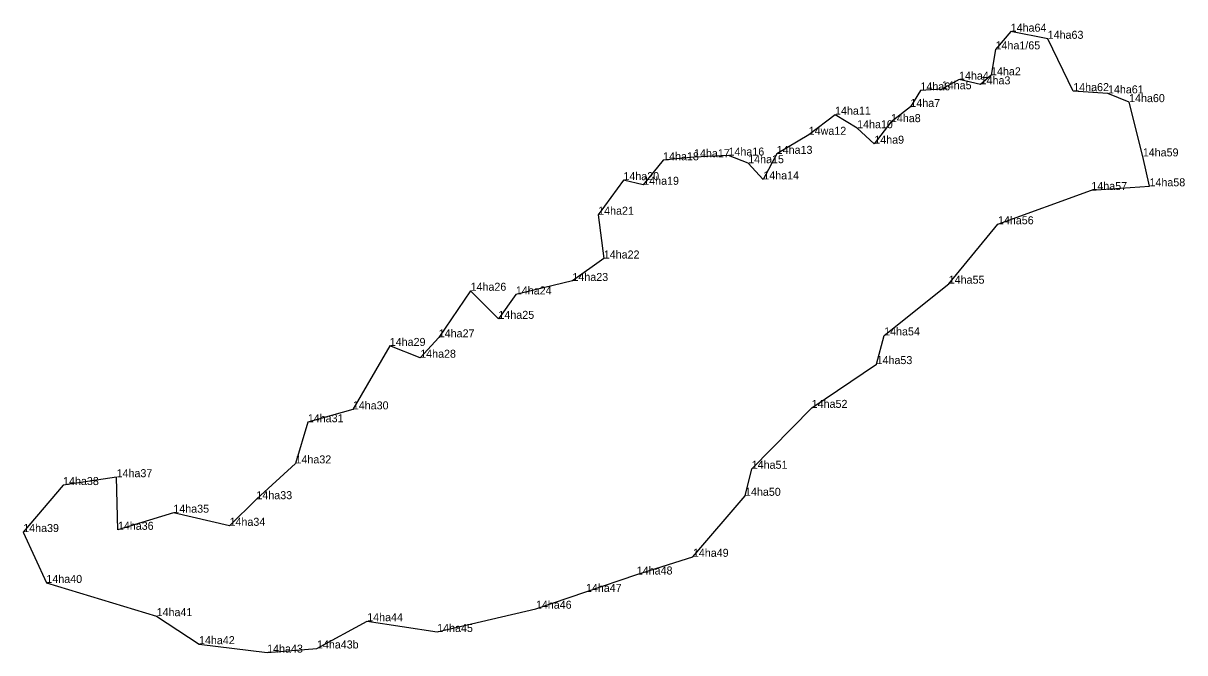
# Model space of a CAD drawing. Extents: x 2072529 to 2267990, y 436423 to 470008.
# Drawn here: x 2254865 to 2255590, y 442680 to 443073 of the extents above; entities that cross this region are included whole.
import ezdxf

# ---------------------------------------------------------------- set-up
doc = ezdxf.new("R2010")
doc.units = 0
doc.layers.add('Level 3', color=7, linetype='Continuous')
doc.layers.add('Old_Level_52', color=7, linetype='Continuous')

msp = doc.modelspace()

# ---------------------------------------------------------------- linework, layer by layer
at = {"layer": 'Level 3'}
for p, q in [((2255481.413, 443068.129), (2255481.413, 443068.129)), ((2255504.521, 443063.666), (2255504.521, 443063.666)), ((2255471.952, 443057.071), (2255471.952, 443057.071)), ((2255469.116, 443040.862), (2255469.116, 443040.862)), ((2255438.396, 443032.173), (2255438.396, 443032.173)), ((2255449.13, 443038.154), (2255449.13, 443038.154)), ((2255462.621, 443035.22), (2255462.621, 443035.22)), ((2255425.047, 443031.446), (2255425.047, 443031.446)), ((2255520.479, 443030.967), (2255520.479, 443030.967)), ((2255542.182, 443029.573), (2255542.182, 443029.573)), ((2255418.747, 443021.084), (2255418.747, 443021.084)), ((2255555.382, 443024.112), (2255555.382, 443024.112)), ((2255371.686, 443016.272), (2255371.686, 443016.272)), ((2255406.582, 443011.611), (2255406.582, 443011.611)), ((2255355.235, 443003.712), (2255355.235, 443003.712)), ((2255385.488, 443007.797), (2255385.488, 443007.797)), ((2255396.2, 442998.156), (2255396.2, 442998.156)), ((2255283.573, 442989.698), (2255283.573, 442989.698)), ((2255305.132, 442990.747), (2255305.132, 442990.747)), ((2255335.25, 442991.808), (2255335.25, 442991.808)), ((2255563.945, 442990.217), (2255563.945, 442990.217)), ((2255264.276, 442987.808), (2255264.276, 442987.808)), ((2255317.443, 442985.98), (2255317.443, 442985.98)), ((2255239.474, 442975.377), (2255239.474, 442975.377)), ((2255326.876, 442975.844), (2255326.876, 442975.844)), ((2255251.851, 442972.495), (2255251.851, 442972.495)), ((2255531.816, 442969.227), (2255531.816, 442969.227)), ((2255568.137, 442971.531), (2255568.137, 442971.531)), ((2255223.707, 442953.789), (2255223.707, 442953.789)), ((2255473.447, 442947.829), (2255473.447, 442947.829)), ((2255227.216, 442926.445), (2255227.216, 442926.445)), ((2255207.631, 442912.408), (2255207.631, 442912.408)), ((2255442.708, 442910.711), (2255442.708, 442910.711)), ((2255143.99, 442906.301), (2255143.99, 442906.301)), ((2255172.269, 442903.968), (2255172.269, 442903.968)), ((2255161.405, 442888.756), (2255161.405, 442888.756)), ((2255124.118, 442877.202), (2255124.118, 442877.202)), ((2255402.364, 442878.396), (2255402.364, 442878.396)), ((2255093.509, 442871.834), (2255093.509, 442871.834)), ((2255112.525, 442864.463), (2255112.525, 442864.463)), ((2255397.633, 442860.486), (2255397.633, 442860.486)), ((2255070.434, 442832.2), (2255070.434, 442832.2)), ((2255357.112, 442833.15), (2255357.112, 442833.15)), ((2255042.302, 442824.17), (2255042.302, 442824.17)), ((2255034.622, 442798.466), (2255034.622, 442798.466)), ((2255319.639, 442795.103), (2255319.639, 442795.103)), ((2254922.848, 442789.849), (2254922.848, 442789.849)), ((2254889.427, 442784.937), (2254889.427, 442784.937)), ((2255315.435, 442778.227), (2255315.435, 442778.227)), ((2255010.212, 442776.108), (2255010.212, 442776.108)), ((2254958.292, 442767.667), (2254958.292, 442767.667)), ((2254923.655, 442756.992), (2254923.655, 442756.992)), ((2254993.406, 442759.479), (2254993.406, 442759.479)), ((2254864.518, 442755.587), (2254864.518, 442755.587)), ((2255282.87, 442740.119), (2255282.87, 442740.119)), ((2255247.82, 442729.064), (2255247.82, 442729.064)), ((2254878.994, 442723.791), (2254878.994, 442723.791)), ((2255216.055, 442718.196), (2255216.055, 442718.196)), ((2255184.802, 442707.683), (2255184.802, 442707.683)), ((2254947.848, 442703.048), (2254947.848, 442703.048)), ((2255079.422, 442699.902), (2255079.422, 442699.902)), ((2255123.125, 442693.157), (2255123.125, 442693.157)), ((2254974.326, 442685.558), (2254974.326, 442685.558)), ((2255016.904, 442680.256), (2255016.904, 442680.256)), ((2255048.013, 442682.864), (2255048.013, 442682.864))]:
    msp.add_line(p, q, dxfattribs=at)
at = {"layer": 'Old_Level_52'}
msp.add_lwpolyline([(2255471.952, 443057.071), (2255469.116, 443040.862), (2255462.621, 443035.22), (2255449.13, 443038.154), (2255438.396, 443032.173), (2255425.047, 443031.446), (2255418.747, 443021.084), (2255406.582, 443011.611), (2255396.2, 442998.156), (2255385.488, 443007.797), (2255371.686, 443016.272), (2255355.235, 443003.712), (2255335.25, 442991.808), (2255326.876, 442975.844), (2255317.443, 442985.98), (2255305.132, 442990.747), (2255283.573, 442989.698), (2255264.276, 442987.808), (2255251.851, 442972.495), (2255239.474, 442975.377), (2255223.707, 442953.789), (2255227.216, 442926.445), (2255207.631, 442912.408), (2255172.269, 442903.968), (2255161.405, 442888.756), (2255143.99, 442906.301), (2255124.118, 442877.202), (2255112.525, 442864.463), (2255093.509, 442871.834), (2255070.434, 442832.2), (2255042.302, 442824.17), (2255034.622, 442798.466), (2255010.212, 442776.108), (2254993.406, 442759.479), (2254958.292, 442767.667), (2254923.655, 442756.992), (2254922.848, 442789.849), (2254889.427, 442784.937), (2254864.518, 442755.587), (2254878.994, 442723.791), (2254947.848, 442703.048), (2254974.326, 442685.558), (2255016.904, 442680.256), (2255048.013, 442682.864), (2255079.422, 442699.902), (2255123.125, 442693.157), (2255184.802, 442707.683), (2255216.055, 442718.196), (2255247.82, 442729.064), (2255282.87, 442740.119), (2255315.435, 442778.227), (2255319.639, 442795.103), (2255357.112, 442833.15), (2255397.633, 442860.486), (2255402.364, 442878.396), (2255442.708, 442910.711), (2255473.447, 442947.829), (2255531.816, 442969.227), (2255568.137, 442971.531), (2255563.945, 442990.217), (2255555.382, 443024.112), (2255542.182, 443029.573), (2255520.479, 443030.967), (2255504.521, 443063.666), (2255481.413, 443068.129)], close=True, dxfattribs=at)

# ---------------------------------------------------------------- texts
for s, p in [('14ha64', (2255481.413, 443068.129)), ('14ha63', (2255504.521, 443063.666)), ('14ha1/65', (2255471.952, 443057.071)), ('14ha4', (2255449.13, 443038.154)), ('14ha3', (2255462.621, 443035.22)), ('14ha2', (2255469.116, 443040.862)), ('14ha6', (2255425.047, 443031.446)), ('14ha5', (2255438.396, 443032.173)), ('14ha62', (2255520.479, 443030.967)), ('14ha61', (2255542.182, 443029.573)), ('14ha7', (2255418.747, 443021.084)), ('14ha60', (2255555.382, 443024.112)), ('14ha11', (2255371.686, 443016.272)), ('14ha10', (2255385.488, 443007.797)), ('14ha8', (2255406.582, 443011.611)), ('14wa12', (2255355.235, 443003.712)), ('14ha9', (2255396.2, 442998.156)), ('14ha16', (2255305.132, 442990.747)), ('14ha13', (2255335.25, 442991.808)), ('14ha18', (2255264.276, 442987.808)), ('14ha17', (2255283.573, 442989.698)), ('14ha15', (2255317.443, 442985.98)), ('14ha59', (2255563.945, 442990.217)), ('14ha20', (2255239.474, 442975.377)), ('14ha19', (2255251.851, 442972.495)), ('14ha14', (2255326.876, 442975.844)), ('14ha57', (2255531.816, 442969.227)), ('14ha58', (2255568.137, 442971.531)), ('14ha21', (2255223.707, 442953.789)), ('14ha56', (2255473.447, 442947.829)), ('14ha22', (2255227.216, 442926.445)), ('14ha23', (2255207.631, 442912.408)), ('14ha55', (2255442.708, 442910.711)), ('14ha26', (2255143.99, 442906.301)), ('14ha24', (2255172.269, 442903.968)), ('14ha25', (2255161.405, 442888.756)), ('14ha27', (2255124.118, 442877.202)), ('14ha54', (2255402.364, 442878.396)), ('14ha29', (2255093.509, 442871.834)), ('14ha28', (2255112.525, 442864.463)), ('14ha53', (2255397.633, 442860.486)), ('14ha30', (2255070.434, 442832.2)), ('14ha52', (2255357.112, 442833.15)), ('14ha31', (2255042.302, 442824.17)), ('14ha32', (2255034.622, 442798.466)), ('14ha51', (2255319.639, 442795.103)), ('14ha37', (2254922.848, 442789.849)), ('14ha38', (2254889.427, 442784.937)), ('14ha33', (2255010.212, 442776.108)), ('14ha50', (2255315.435, 442778.227)), ('14ha35', (2254958.292, 442767.667)), ('14ha34', (2254993.406, 442759.479)), ('14ha39', (2254864.518, 442755.587)), ('14ha36', (2254923.655, 442756.992)), ('14ha49', (2255282.87, 442740.119)), ('14ha40', (2254878.994, 442723.791)), ('14ha48', (2255247.82, 442729.064)), ('14ha47', (2255216.055, 442718.196)), ('14ha46', (2255184.802, 442707.683)), ('14ha41', (2254947.848, 442703.048)), ('14ha44', (2255079.422, 442699.902)), ('14ha45', (2255123.125, 442693.157)), ('14ha42', (2254974.326, 442685.558)), ('14ha43', (2255016.904, 442680.256)), ('14ha43b', (2255048.013, 442682.864))]:
    msp.add_text(s, height=5).set_placement(p)

doc.saveas('drawing.dxf')
